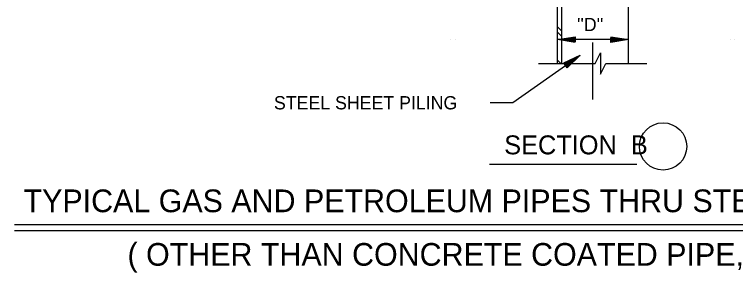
# Model space of a CAD drawing. Extents: x 22339.2 to 22413.4, y 22369.6 to 22418.8.
# Drawn here: x 22374.62 to 22384.77, y 22380.91 to 22384.55 of the extents above; entities that cross this region are included whole.
import ezdxf

# ---------------------------------------------------------------- set-up
doc = ezdxf.new("R2010")
doc.units = 0
for name, color, linetype in [('Level 1', 7, 'Continuous'), ('Level 10', 7, 'Continuous'), ('Level 2', 7, 'Continuous'), ('Level 3', 7, 'Continuous'), ('Level 4', 7, 'Continuous'), ('Level 8', 7, 'Continuous')]:
    doc.layers.add(name, color=color, linetype=linetype)

msp = doc.modelspace()

# ---------------------------------------------------------------- linework, layer by layer
at = {"layer": 'Level 1'}
for p, q in [((22380.764, 22384.195), (22380.764, 22384.195)), ((22380.833, 22384.195), (22380.833, 22384.195)), ((22383.266, 22384.195), (22382.266, 22384.195)), ((22382.697, 22384.195), (22382.697, 22384.195)), ((22382.766, 22384.195), (22382.766, 22384.195)), ((22382.766, 22384.195), (22382.766, 22384.195)), ((22382.835, 22384.195), (22382.835, 22384.195)), ((22384.697, 22384.195), (22384.697, 22384.195)), ((22384.766, 22384.195), (22384.766, 22384.195)), ((22382.766, 22383.351), (22382.766, 22384.154)), ((22382.528, 22383.936), (22382.528, 22383.936)), ((22382.585, 22383.976), (22382.585, 22383.976)), ((22382, 22383.857), (22382.798, 22383.857)), ((22382.947, 22383.857), (22383.527, 22383.857))]:
    msp.add_line(p, q, dxfattribs=at)
msp.add_lwpolyline([(22382.798, 22383.857), (22382.872, 22384.007), (22382.872, 22383.707), (22382.947, 22383.857)], dxfattribs=at)
at = {"layer": 'Level 10'}
for p, q in [((22381.311, 22382.441), (22383.382, 22382.441)), ((22374.622, 22381.589), (22390.943, 22381.589)), ((22374.622, 22381.505), (22390.963, 22381.505))]:
    msp.add_line(p, q, dxfattribs=at)
at = {"layer": 'Level 2'}
for p, q in [((22382.266, 22383.857), (22382.266, 22386.967)), ((22382.328, 22383.857), (22382.328, 22386.967)), ((22383.266, 22383.857), (22383.266, 22386.967))]:
    msp.add_line(p, q, dxfattribs=at)
for points in [[(22382.515, 22384.153), (22382.266, 22384.195), (22382.515, 22384.236), (22382.515, 22384.165), (22382.335, 22384.195), (22382.505, 22384.223), (22382.505, 22384.177), (22382.402, 22384.195), (22382.494, 22384.209), (22382.494, 22384.191), (22382.471, 22384.195)], [(22383.017, 22384.236), (22383.266, 22384.195), (22383.017, 22384.153), (22383.017, 22384.224), (22383.197, 22384.195), (22383.027, 22384.167), (22383.027, 22384.212), (22383.13, 22384.195), (22383.038, 22384.18), (22383.038, 22384.199), (22383.061, 22384.195)], [(22381.32, 22383.307), (22381.64, 22383.307), (22382.585, 22383.976)], [(22382.358, 22383.866), (22382.585, 22383.976), (22382.405, 22383.798), (22382.365, 22383.856), (22382.528, 22383.936), (22382.406, 22383.815), (22382.38, 22383.852), (22382.474, 22383.898), (22382.407, 22383.832), (22382.397, 22383.848), (22382.417, 22383.858)]]:
    msp.add_lwpolyline(points, dxfattribs=at)
at = {"layer": 'Level 3'}
msp.add_circle((22383.754, 22382.69), 0.333, dxfattribs=at)
at = {"layer": 'Level 8'}
for p, q in [((22382.266, 22384.195), (22382.266, 22384.195)), ((22382.335, 22384.195), (22382.335, 22384.195)), ((22383.197, 22384.195), (22383.197, 22384.195)), ((22383.266, 22384.195), (22383.266, 22384.195))]:
    msp.add_line(p, q, dxfattribs=at)
for points in [[(22382.328, 22384.314), (22382.266, 22384.376)], [(22382.328, 22384.239), (22382.266, 22384.301)], [(22382.314, 22383.857), (22382.266, 22383.905)]]:
    msp.add_lwpolyline(points, dxfattribs=at)

# ---------------------------------------------------------------- texts
at = {"layer": 'Level 3'}
for s, height, p in [('SECTION  B', 0.2667, (22381.517, 22382.579)), ('TYPICAL GAS AND PETROLEUM PIPES THRU STEEL SHEET PILING', 0.32, (22374.751, 22381.764)), ('( OTHER THAN CONCRETE COATED PIPE, OPTION 2 )', 0.32, (22376.214, 22381.01))]:
    msp.add_text(s, height=height, dxfattribs=at).set_placement(p)
at = {"layer": 'Level 4'}
for s, height, p in [("''D''", 0.1867, (22382.543, 22384.315)), ('STEEL SHEET PILING', 0.18667, (22378.276, 22383.212))]:
    msp.add_text(s, height=height, dxfattribs=at).set_placement(p)

doc.saveas('drawing.dxf')
